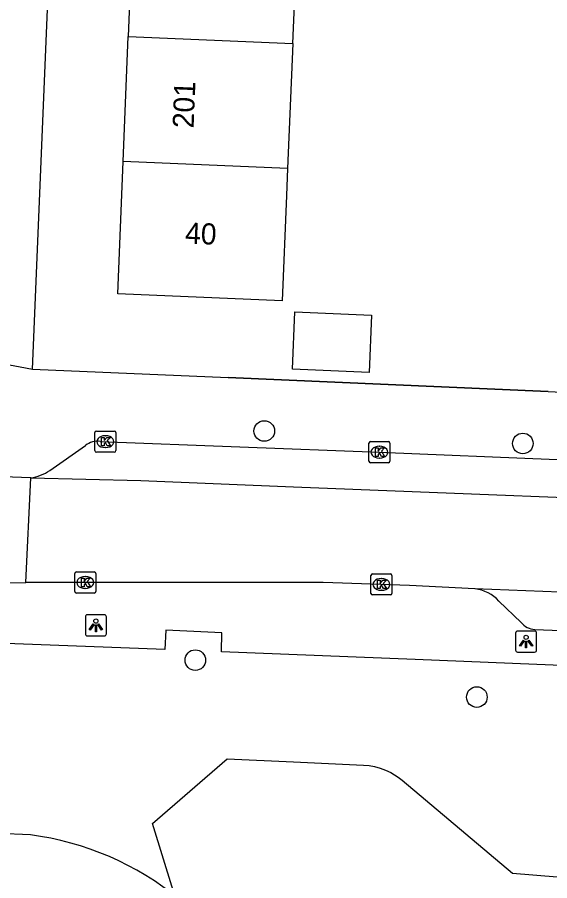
# Model space of a CAD drawing. Extents: x 159822 to 160765, y 380693 to 381634.
# Drawn here: x 159986.9 to 160012.17, y 380857.77 to 380898.7 of the extents above; entities that cross this region are included whole.
import ezdxf

# ---------------------------------------------------------------- set-up
doc = ezdxf.new("R2010")
doc.units = 0
for name, color, linetype in [('IMGEO_Berm_groen', 7, 'Continuous'), ('IMGEO_Boom', 7, 'Continuous'), ('IMGEO_Fietspad_gesloten', 7, 'Continuous'), ('IMGEO_Kolk', 7, 'Continuous'), ('IMGEO_Lichtpunt', 7, 'Continuous'), ('IMGEO_Muur', 7, 'Continuous'), ('IMGEO_Pand', 7, 'Continuous'), ('IMGEO_Pand_nummerreeks', 7, 'Continuous'), ('IMGEO_Rijbaan_lokaal_open', 7, 'Continuous'), ('IMGEO_Voetpad_open', 7, 'Continuous')]:
    doc.layers.add(name, color=color, linetype=linetype)

msp = doc.modelspace()

# ---------------------------------------------------------------- linework, layer by layer
at = {"layer": 'IMGEO_Berm_groen'}
msp.add_lwpolyline([(159994.3, 380857.307), (159993.316, 380860.49), (159996.856, 380863.546), (160000, 380863.404), (160003.334, 380863.253), (160003.59, 380863.231), (160003.849, 380863.185), (160004.112, 380863.115), (160004.374, 380863.02), (160004.624, 380862.902), (160004.804, 380862.798), (160004.973, 380862.685), (160005.16, 380862.539), (160010.391, 380858.132), (160044.707, 380855.323), (160053.703, 380854.587), (160080.604, 380853.22), (160134.865, 380851.138), (160141.219, 380857.313), (160149.892, 380857.411), (160158.085, 380851.531), (160156.14, 380847.719)], dxfattribs=at)
at = {"layer": 'IMGEO_Boom'}
for centre in [(159998.618, 380879.089), (160010.889, 380878.497), (159995.347, 380868.229), (160008.708, 380866.477)]:
    msp.add_circle(centre, 0.489, dxfattribs=at)
at = {"layer": 'IMGEO_Fietspad_gesloten'}
msp.add_lwpolyline([(159987.519, 380859.942), (159984.435, 380860.069)], dxfattribs=at)
msp.add_arc((159985.754, 380846.132), 13.922, 50.6046, 82.7169, dxfattribs=at)
at = {"layer": 'IMGEO_Kolk'}
for p, q in [((159990.577, 380878.161), (159990.577, 380879.013)), ((159990.652, 380879.087), (159991.504, 380879.087)), ((159991.065, 380878.867), (159991.09, 380878.867)), ((159991.578, 380879.013), (159991.578, 380878.161)), ((160003.584, 380877.659), (160003.584, 380878.511)), ((160003.659, 380878.585), (160004.511, 380878.585)), ((160004.585, 380878.511), (160004.585, 380877.659)), ((159991.504, 380878.087), (159990.652, 380878.087)), ((159991.088, 380878.307), (159991.063, 380878.307)), ((160004.072, 380878.365), (160004.097, 380878.365)), ((160004.095, 380877.805), (160004.07, 380877.805)), ((160004.511, 380877.585), (160003.659, 380877.585)), ((159989.626, 380871.481), (159989.626, 380872.333)), ((159989.701, 380872.407), (159990.553, 380872.407)), ((159990.627, 380872.333), (159990.627, 380871.481)), ((160003.752, 380872.317), (160004.604, 380872.317)), ((159990.114, 380872.187), (159990.139, 380872.187)), ((160003.677, 380871.391), (160003.677, 380872.243)), ((160004.165, 380872.097), (160004.19, 380872.097)), ((160004.678, 380872.243), (160004.678, 380871.391)), ((159990.137, 380871.627), (159990.112, 380871.627)), ((160004.188, 380871.537), (160004.163, 380871.537)), ((159990.553, 380871.407), (159989.701, 380871.407)), ((160004.604, 380871.317), (160003.752, 380871.317))]:
    msp.add_line(p, q, dxfattribs=at)
for points in [[(159990.577, 380878.161), (159990.577, 380879.013)], [(159990.652, 380879.087), (159991.504, 380879.087)], [(159991.578, 380879.013), (159991.578, 380878.161)], [(159990.898, 380878.787), (159991.021, 380878.787), (159991.021, 380878.636), (159991.151, 380878.787), (159991.315, 380878.787), (159991.169, 380878.636), (159991.322, 380878.387), (159991.17, 380878.387), (159991.085, 380878.551), (159991.021, 380878.484), (159991.021, 380878.387), (159990.898, 380878.387), (159990.898, 380878.787)], [(160003.584, 380877.659), (160003.584, 380878.511)], [(160003.659, 380878.585), (160004.511, 380878.585)], [(160004.585, 380878.511), (160004.585, 380877.659)], [(159991.504, 380878.087), (159990.652, 380878.087)], [(160003.905, 380878.285), (160004.028, 380878.285), (160004.028, 380878.134), (160004.158, 380878.285), (160004.322, 380878.285), (160004.176, 380878.134), (160004.329, 380877.885), (160004.177, 380877.885), (160004.092, 380878.049), (160004.028, 380877.982), (160004.028, 380877.885), (160003.905, 380877.885), (160003.905, 380878.285)], [(160004.511, 380877.585), (160003.659, 380877.585)], [(159989.626, 380871.481), (159989.626, 380872.333)], [(159989.701, 380872.407), (159990.553, 380872.407)], [(159990.627, 380872.333), (159990.627, 380871.481)], [(160003.752, 380872.317), (160004.604, 380872.317)], [(159989.947, 380872.107), (159990.07, 380872.107), (159990.07, 380871.956), (159990.2, 380872.107), (159990.364, 380872.107), (159990.218, 380871.956), (159990.371, 380871.707), (159990.219, 380871.707), (159990.134, 380871.871), (159990.07, 380871.804), (159990.07, 380871.707), (159989.947, 380871.707), (159989.947, 380872.107)], [(160003.677, 380871.391), (160003.677, 380872.243)], [(160003.998, 380872.017), (160004.121, 380872.017), (160004.121, 380871.866), (160004.251, 380872.017), (160004.415, 380872.017), (160004.269, 380871.866), (160004.422, 380871.617), (160004.27, 380871.617), (160004.185, 380871.781), (160004.121, 380871.714), (160004.121, 380871.617), (160003.998, 380871.617), (160003.998, 380872.017)], [(160004.678, 380872.243), (160004.678, 380871.391)], [(159990.553, 380871.407), (159989.701, 380871.407)], [(160004.604, 380871.317), (160003.752, 380871.317)]]:
    msp.add_lwpolyline(points, dxfattribs=at)
for centre, start, end in [((159990.654, 380879.011), 91.552, 178.448), ((159990.654, 380879.011), 91.552, 178.448), ((159991.502, 380879.011), 1.552, 88.448), ((159991.502, 380879.011), 1.552, 88.448), ((160003.661, 380878.509), 91.552, 178.448), ((160003.661, 380878.509), 91.552, 178.448), ((160004.509, 380878.509), 1.552, 88.448), ((160004.509, 380878.509), 1.552, 88.448), ((159990.654, 380878.163), 181.552, 268.448), ((159990.654, 380878.163), 181.552, 268.448), ((159991.502, 380878.163), 271.552, 358.448), ((159991.502, 380878.163), 271.552, 358.448), ((160003.661, 380877.661), 181.552, 268.448), ((160003.661, 380877.661), 181.552, 268.448), ((160004.509, 380877.661), 271.552, 358.448), ((160004.509, 380877.661), 271.552, 358.448), ((159989.703, 380872.331), 91.552, 178.448), ((159989.703, 380872.331), 91.552, 178.448), ((159990.551, 380872.331), 1.552, 88.448), ((159990.551, 380872.331), 1.552, 88.448), ((160003.754, 380872.241), 91.552, 178.448), ((160003.754, 380872.241), 91.552, 178.448), ((160004.602, 380872.241), 1.552, 88.448), ((160004.602, 380872.241), 1.552, 88.448), ((159989.703, 380871.483), 181.552, 268.448), ((159989.703, 380871.483), 181.552, 268.448), ((159990.551, 380871.483), 271.552, 358.448), ((159990.551, 380871.483), 271.552, 358.448), ((160003.754, 380871.393), 181.552, 268.448), ((160003.754, 380871.393), 181.552, 268.448), ((160004.602, 380871.393), 271.552, 358.448), ((160004.602, 380871.393), 271.552, 358.448)]:
    msp.add_arc(centre, 0.0765, start, end, dxfattribs=at)
for centre, major_axis, ratio, start_param, end_param in [((159991.064, 380878.587), (-0.387, 0.002), 0.722429, 4.712389, 7.853982), ((159991.089, 380878.587), (-0.39, 0.002), 0.717154, 1.570796, 4.712389), ((160004.071, 380878.085), (-0.387, 0.002), 0.722429, 4.712389, 7.853982), ((160004.096, 380878.085), (-0.39, 0.002), 0.717154, 1.570796, 4.712389), ((159990.113, 380871.907), (-0.387, 0.002), 0.722429, 4.712389, 7.853982), ((159990.138, 380871.907), (-0.39, 0.002), 0.717154, 1.570796, 4.712389), ((160004.164, 380871.817), (-0.387, 0.002), 0.722429, 4.712389, 7.853982), ((160004.189, 380871.817), (-0.39, 0.002), 0.717154, 1.570796, 4.712389)]:
    msp.add_ellipse(centre, major_axis=major_axis, ratio=ratio, start_param=start_param, end_param=end_param, dxfattribs=at)
at = {"layer": 'IMGEO_Lichtpunt'}
for p, q in [((159990.129, 380870.282), (159990.129, 380869.475)), ((159990.129, 380870.282), (159990.129, 380869.475)), ((159991.031, 380870.377), (159990.223, 380870.377)), ((159991.031, 380870.377), (159990.223, 380870.377)), ((159991.125, 380869.475), (159991.125, 380870.282)), ((159991.125, 380869.475), (159991.125, 380870.282)), ((160010.547, 380869.51), (160010.547, 380868.703)), ((160010.547, 380869.51), (160010.547, 380868.703)), ((160011.449, 380869.605), (160010.641, 380869.605)), ((160011.449, 380869.605), (160010.641, 380869.605)), ((160011.543, 380868.703), (160011.543, 380869.51)), ((160011.543, 380868.703), (160011.543, 380869.51)), ((159990.223, 380869.381), (159991.031, 380869.381)), ((159990.223, 380869.381), (159991.031, 380869.381)), ((160010.641, 380868.609), (160011.449, 380868.609)), ((160010.641, 380868.609), (160011.449, 380868.609))]:
    msp.add_line(p, q, dxfattribs=at)
for points in [[(159990.503, 380869.946), (159990.542, 380869.918), (159990.354, 380869.656), (159990.316, 380869.683), (159990.503, 380869.946)], [(159990.605, 380869.898), (159990.652, 380869.898), (159990.652, 380869.576), (159990.605, 380869.576), (159990.605, 380869.898)], [(159990.715, 380869.918), (159990.753, 380869.945), (159990.94, 380869.683), (159990.901, 380869.655), (159990.715, 380869.918)], [(160010.921, 380869.174), (160010.96, 380869.146), (160010.772, 380868.884), (160010.734, 380868.911), (160010.921, 380869.174)], [(160011.023, 380869.126), (160011.07, 380869.126), (160011.07, 380868.804), (160011.023, 380868.804), (160011.023, 380869.126)], [(160011.133, 380869.146), (160011.171, 380869.173), (160011.358, 380868.911), (160011.319, 380868.883), (160011.133, 380869.146)]]:
    msp.add_lwpolyline(points, dxfattribs=at)
for centre in [(159990.628, 380870.08), (160011.046, 380869.308)]:
    msp.add_circle(centre, 0.0994, dxfattribs=at)
for centre, start, end in [((159990.223, 380870.282), 90, 180), ((159990.223, 380870.282), 90, 180), ((159991.031, 380870.282), 0, 90), ((159991.031, 380870.282), 0, 90), ((159990.223, 380869.475), 180, 270), ((159990.223, 380869.475), 180, 270), ((159991.031, 380869.475), 270, 0), ((159991.031, 380869.475), 270, 360), ((160010.641, 380869.51), 90, 180), ((160010.641, 380869.51), 90, 180), ((160011.449, 380869.51), 0, 90), ((160011.449, 380869.51), 0, 90), ((160010.641, 380868.703), 180, 270), ((160010.641, 380868.703), 180, 270), ((160011.449, 380868.703), 270, 0), ((160011.449, 380868.703), 270, 360)]:
    msp.add_arc(centre, 0.0946, start, end, dxfattribs=at)
at = {"layer": 'IMGEO_Muur'}
msp.add_lwpolyline([(160012.088, 380880.965), (159996.902, 380881.622)], dxfattribs=at)
at = {"layer": 'IMGEO_Pand'}
for points in [[(159992.4, 380903.707), (159992.159, 380897.782)], [(159999.978, 380897.453), (160000.227, 380903.378)], [(159991.918, 380891.856), (159992.159, 380897.782)], [(159992.159, 380897.782), (159999.978, 380897.453)], [(159999.978, 380897.453), (159999.729, 380891.528)], [(159999.729, 380891.528), (159999.676, 380890.259), (159999.466, 380885.263), (159991.663, 380885.591), (159991.918, 380891.856)], [(159999.729, 380891.528), (159991.918, 380891.856)], [(160003.715, 380884.585), (160003.6, 380881.868), (159999.959, 380882.021), (160000.073, 380884.738), (160003.715, 380884.585)]]:
    msp.add_lwpolyline(points, dxfattribs=at)
at = {"layer": 'IMGEO_Rijbaan_lokaal_open'}
for points in [[(159987.534, 380876.872), (159983.589, 380877.007)], [(159987.308, 380871.906), (159987.534, 380876.872)], [(159987.534, 380876.872), (159992.758, 380876.736), (160000, 380876.443), (160043.442, 380874.732)], [(159984.118, 380871.793), (159985.324, 380871.897), (159987.308, 380871.906)], [(160008.619, 380871.611), (160005.518, 380871.771), (160001.409, 380871.913), (159987.308, 380871.906)], [(160037.659, 380870.474), (160008.619, 380871.611)]]:
    msp.add_lwpolyline(points, dxfattribs=at)
at = {"layer": 'IMGEO_Voetpad_open'}
for points in [[(159987.614, 380882.024), (159989.985, 380938.498)], [(159984.501, 380882.6), (159987.614, 380882.024)], [(159987.614, 380882.024), (159996.902, 380881.622), (160012.088, 380880.965), (160015.8, 380880.79)], [(159990.838, 380878.596), (160004.085, 380878.085), (160012.514, 380877.733), (160015.362, 380877.62), (160040.886, 380876.611)], [(159988.442, 380877.212), (159990.132, 380878.405)], [(160009.754, 380871.026), (160010.803, 380870.019)], [(160169.444, 380861.549), (160005.773, 380868.257), (159996.586, 380868.629), (159996.603, 380869.516), (159993.946, 380869.644), (159993.895, 380868.739), (159985.923, 380869.026)], [(160011.462, 380869.688), (160034.506, 380868.789)]]:
    msp.add_lwpolyline(points, dxfattribs=at)
for centre, radius, start, end in [((159990.718, 380877.639), 0.964, 82.8464, 127.4302), ((159987.258, 380878.991), 2.137, 277.417, 303.6397), ((160008.396, 380869.784), 1.841, 42.437, 83.0281), ((160011.48, 380870.545), 0.857, 217.8393, 268.8221)]:
    msp.add_arc(centre, radius, start, end, dxfattribs=at)

# ---------------------------------------------------------------- texts
at = {"layer": 'IMGEO_Pand_nummerreeks'}
for s, rotation, p in [('201', 87.6689, (159995.265, 380893.423)), ('40', 357.593, (159994.848, 380887.979))]:
    msp.add_text(s, height=1, rotation=rotation, dxfattribs=at).set_placement(p)

doc.saveas('drawing.dxf')
